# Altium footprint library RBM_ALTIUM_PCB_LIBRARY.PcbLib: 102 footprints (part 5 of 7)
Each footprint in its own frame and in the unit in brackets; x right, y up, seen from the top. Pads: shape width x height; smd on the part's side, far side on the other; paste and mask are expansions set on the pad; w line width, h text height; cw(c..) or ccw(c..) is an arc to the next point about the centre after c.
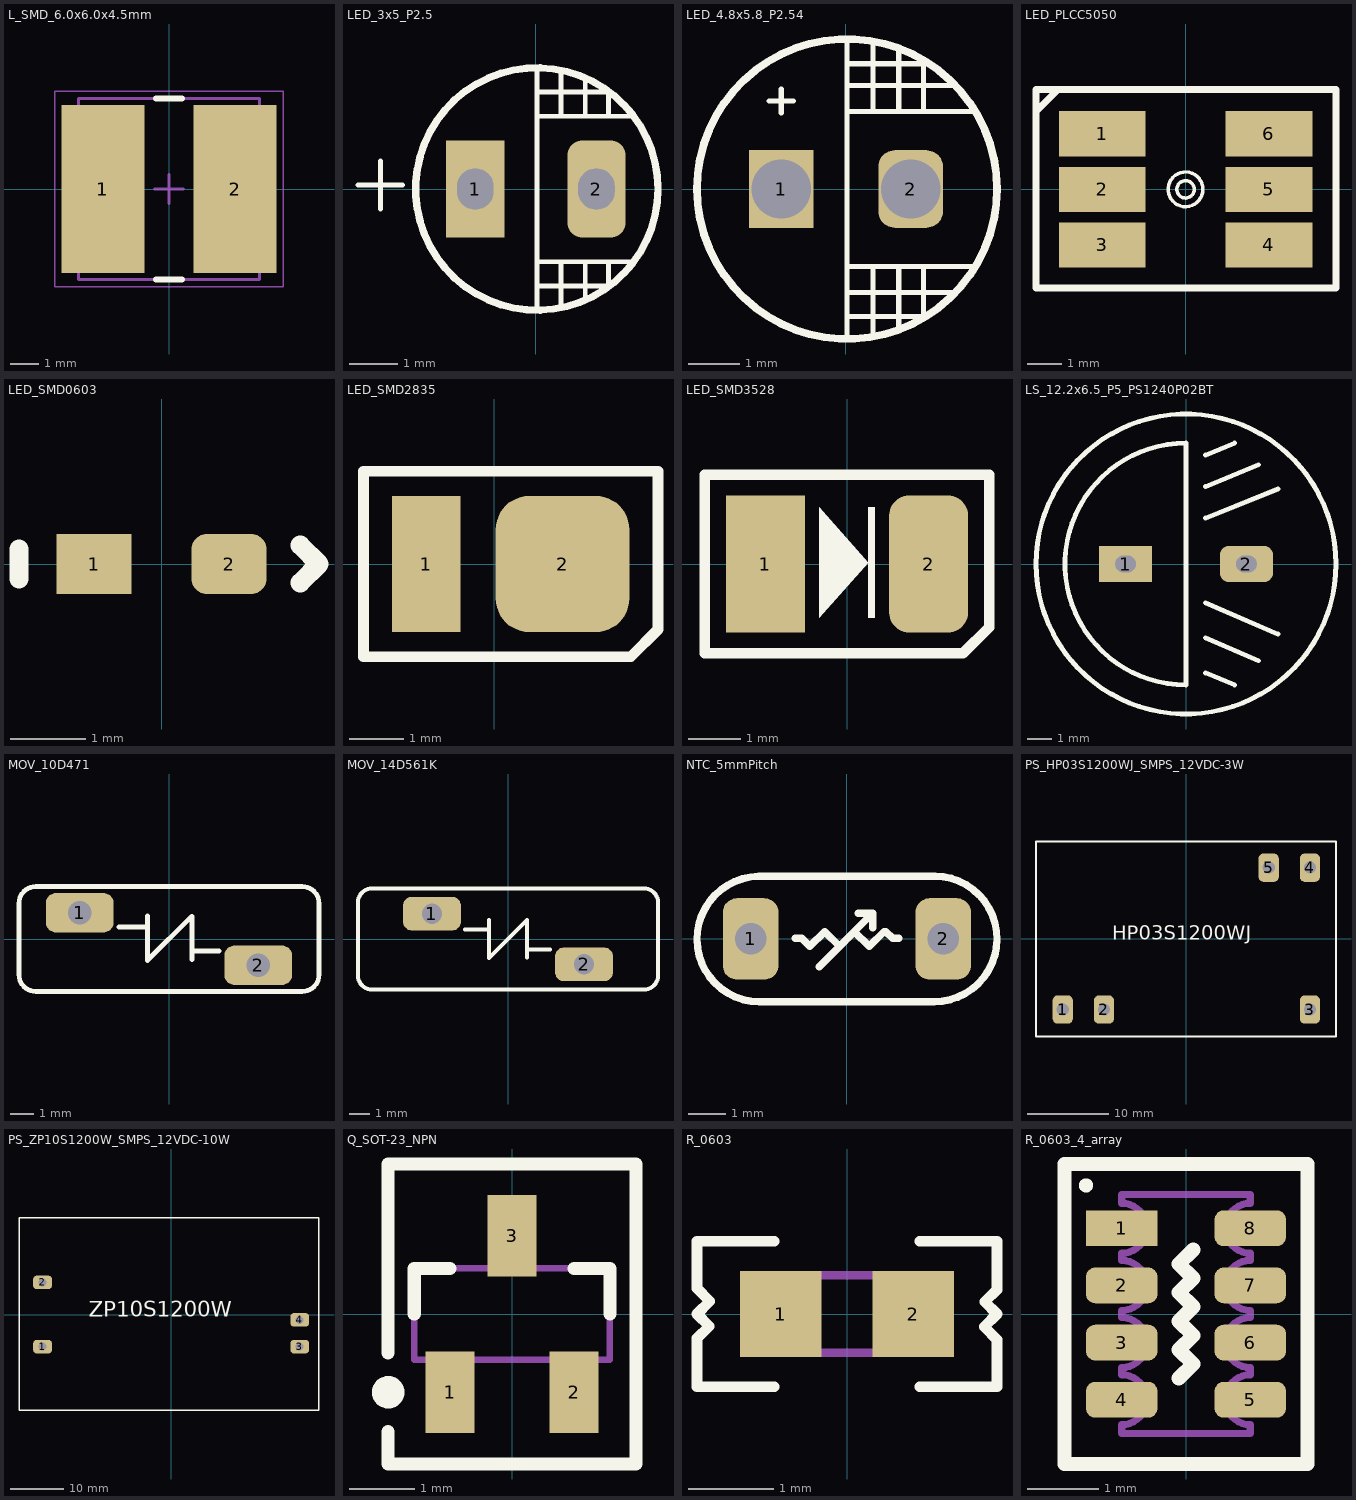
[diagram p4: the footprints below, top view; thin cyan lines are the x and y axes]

## L_SMD_6.0x6.0x4.5mm [mm] "YNR6045-102M;  1mH ±20% 300mA 4.5O SMD,6.0x6.0x4.5mm Power Inductors RoHS"
height 4.5
pads (2):
  rect 2.9x5.85 smd: 1(-2.3,0) 2(2.3,0)
Top Overlay:
  lines w0.2: -0.45,-3.15 0.45,-3.15 ; -0.45,3.15 0.45,3.15
Assembly Top:
  lines w0.1: -3.15,-3.15 -3.15,3.15 3.15,3.15 3.15,-3.15 -3.15,-3.15
Courtyard Top:
  lines w0.05: -3.975,-3.4 -3.975,3.4 3.975,3.4 3.975,-3.4 -3.975,-3.4
  lines w0.1: -0.5,0 0.5,0 ; 0,-0.5 0,0.5
3D body "INDP6060X45N.step": height 4.6, standoff 0, extent -3.1,-3 3.1,3

## LED_3x5_P2.5 [mm]
pads (2):
  rect 1.2x2 hole 0.85 slot 0.75 at 0 deg: 1(-1.25,0)
  rrect50% 1.2x2 hole 0.85 slot 0.75 at 0 deg: 2(1.25,0)
Top Overlay:
  circle w0.15: c0.02,0 r2.5
  lines w0.1: -3.67,0.083 -2.754,0.083 ; -3.203,-0.417 -3.203,0.583 ; 0.02,-2.5 0.02,2.5 ; 0.02,-2 1.5,-2 1.5,-1.5 ; 0.02,-1.5 2.014,-1.5 ; 0.02,1.5 2.014,1.5 ; 0.02,2 1.5,2 1.5,1.5 ; 0.52,-2.4 0.52,-1.5 ; 0.52,1.5 0.52,2.4 ; 1.02,-2.3 1.02,-1.5 ; 1.02,1.5 1.02,2.3
3D body "LED_3x5_P2.5.STEP": height 7.38, standoff -1.17, extent -1.974,-1.498 2.014,1.994

## LED_4.8x5.8_P2.54 [mm] "HL-798H256WC-MD"
pads (2):
  rect 1.25x1.5 / inner rect 1.5x2.2 / far side rect 1.5x2.2 hole 1.15: 1(-1.25,0)
  rrect50% 1.25x1.5 / inner rrect50% 1.5x2.2 / far side rrect50% 1.5x2.2 hole 1.15: 2(1.25,0)
Top Overlay:
  circle w0.15: c0.02,0 r2.9
  lines w0.1: -1.484,1.7 -1.017,1.7 ; -1.25,1.466 -1.25,1.934 ; 0.02,-2.9 0.02,2.9 ; 0.02,-2 2.1,-2 ; 0.02,-1.5 2.503,-1.5 ; 0.02,1.5 2.502,1.5 ; 0.02,2 2.126,2 ; 0.02,2.423 1.5,2.423 ; 0.039,-2.465 1.5,-2.465 ; 0.52,-2.857 0.52,-1.5 ; 0.52,1.5 0.52,2.857 ; 1.02,-2.722 1.02,-1.5 ; 1.02,1.5 1.02,2.722 ; 1.5,-2.494 1.5,-1.5 ; 1.5,1.5 1.5,2.5
3D body: height 4.8, standoff 0, extent -2.38,-2.4 2.42,2.4
3D body: height 1.5, standoff 0, extent -2.88,-2.897 2.92,2.897
3D body: height 2, standoff 1, extent -1.98,-2 2.02,2
3D body: height 1, standoff -1.5, extent -1.746,-0.499 -0.75,0.499
3D body: height 1, standoff -1.5, extent 0.754,-0.499 1.75,0.499

## LED_PLCC5050 [mm] "EDISON RGB .2W"
pads (6):
  rect 2.5x1.3 smd: 1(-2.4,1.6) 2(-2.4,0) 3(-2.4,-1.6) 4(2.4,-1.6) 5(2.4,0) 6(2.4,1.6)
Top Overlay:
  circle w0.1: c0,0 r0.5
  circle w0.1: c0,0 r0.25
  lines w0.2: -4.305,2.235 -3.67,2.87 ; -4.305,-2.845 4.331,-2.845 4.331,2.87 -4.305,2.87 -4.305,-2.845
3D body "User Library-APA102C.step": height 1.51, standoff -0.04, extent -2.75,-2.5 2.75,2.5

## LED_SMD0603 [mm]
pads (2):
  rect 1x0.8 smd: 1(-0.9,0)
  rrect50% 1x0.8 smd: 2(0.9,0)
Top Overlay:
  lines w0.254: -1.9,-0.2 -1.9,0.2 ; 1.85,-0.25 2.1,0 1.85,0.25
3D body "ALSRobot-LED0603(R).step": height 0.6, standoff 0, extent -0.81,-0.4 0.81,0.4

## LED_SMD2835 [mm]
pads (2):
  rect 1.25x2.5 smd: 1(-1.25,0)
  rrect50% 2.45x2.5 smd: 2(1.25,0)
Top Overlay:
  lines w0.2: -2.4,-1.7 2.5,-1.7 3,-1.2 3,1.7 -2.4,1.7 -2.4,-1.7
3D body "LED_SMD-2835.STEP": height 0.7, standoff -0.02, extent -1.547,-1.4 2.017,1.4

## LED_SMD3528 [mm]
pads (2):
  rect 1.5x2.6 smd: 1(-1.55,0)
  rrect50% 1.5x2.6 smd: 2(1.55,0)
Top Overlay:
  region: 0.525,1.075 0.4,1.075 0.4,-1.025 0.525,-1.025
  region: -0.525,-1.025 -0.525,1.075 0.4,0.025
  region: 2.5,1.6
  lines w0.2: -2.7,-1.7 -2.7,1.7 2.7,1.7 2.7,-1.2 2.2,-1.7 -2.7,-1.7
3D body "LED_Osram_Led_PLCC4-2.step": height 1.95, standoff 0, extent -1.8,-1.4 1.7,1.4

## LS_12.2x6.5_P5_PS1240P02BT [mm] "PS1240P02BT, ø12.2x6.5 P5 70dB 4kHz 3~30V"
pads (2):
  rect 2.2x1.5 hole 0.7 slot 0.85 at 0 deg: 1(-2.5,0)
  rrect50% 2.2x1.5 hole 0.7 slot 0.85 at 0 deg: 2(2.5,0)
Top Overlay:
  circle w0.2: c0,0 r6.2
  lines w0.2: 0.8,-4.5 2,-5 ; 0.8,-3.046 3,-4 ; 0.8,-1.6 3.8,-2.9 ; 0.8,1.9 3.8,3.1 ; 0.8,3.2 3,4.1 ; 0.8,4.5 2,5 ; 0,-5 cw(c0,0) 0,5 0,-5
3D body: height 6.8, standoff 0.3, extent -1.494,-1.497 1.494,1.497
3D body: height 1, standoff -1, extent 2.173,-0.329 2.83,0.33
3D body: height 1, standoff -1, extent -2.829,-0.329 -2.171,0.329
3D body: height 6.75, standoff 0.25, extent -6.1,-6.097 6.1,6.097

## MOV_10D471 [mm]
pads (2):
  rrect50% 2.85x1.65 hole 1: 1(-3.75,1.1) 2(3.75,-1.1)
Top Overlay:
  lines w0.1: 0.998,-0.51 1.009,-0.5
  lines w0.2: -5.1,2.2 5.6,2.2 cw(c5.6,1.5) 6.3,1.5 6.3,-1.5 cw(c5.6,-1.5) 5.6,-2.2 -5.6,-2.2 cw(c-5.6,-1.5) -6.3,-1.5 -6.3,1.5 cw(c-5.6,1.5) -5.6,2.2 -4.9,2.2 ; -2.1,0.499 -0.921,0.499 ; -0.908,0.967 -0.908,-0.903 0.954,0.959 ; 0.967,-0.875 0.967,0.959 ; 1.009,-0.5 2.1,-0.5
3D body: height 3, standoff -2, extent 3.343,-1.509 4.16,-0.691
3D body: height 3, standoff -2, extent -4.158,0.691 -3.342,1.509
3D body "User Library-S10K275.STEP": height 13.55, standoff -1.95, extent -6,-1.9 6,1.901

## MOV_14D561K [mm]
pads (2):
  rrect50% 2.85x1.65 hole 1: 1(-3.75,1.25) 2(3.75,-1.25)
Top Overlay:
  lines w0.1: 0.975,-0.539 0.985,-0.528
  lines w0.2: -2.123,0.471 -0.945,0.471 ; -0.931,0.939 -0.931,-0.931 0.931,0.931 ; 0.944,-0.903 0.944,0.931 ; 0.985,-0.528 2.077,-0.528 ; -7.4,-1.8 ccw(c-6.7,-1.8) -6.7,-2.5 6.7,-2.5 ccw(c6.7,-1.8) 7.4,-1.8 7.4,1.8 ccw(c6.7,1.8) 6.7,2.5 -6.7,2.5 ccw(c-6.7,1.8) -7.4,1.8 -7.4,-1.8
3D body "Varistor_14D561K.STEP": height 17.4, standoff -1.5, extent -7.4,-2.175 7.4,2.175

## NTC_5mmPitch [mm]
pads (2):
  rrect50% 1.5x2.2 hole 0.85: 1(-2.6,0) 2(2.6,0)
Top Overlay:
  lines w0.1: -1.229,0.018 -1.218,0.018 ; 1,0.2 1.049,0.2 ; -0.6,0.2 -0.6,0.2 ; 0.6,-0.2 0.6,-0.2
  lines w0.2: -2.384,1.691 ccw(c-2.353,-0.005) -2.371,-1.7 ; -2.384,1.692 2.38,1.692 ; -2.353,-1.694 2.355,-1.694 ; -1.4,0.018 -1.229,0.018 ; -1.218,0.018 -1,-0.2 -0.6,0.2 -0.2,-0.2 0.2,0.2 0.6,-0.2 1,0.2 ; -0.75,-0.75 0.7,0.7 ; 0.3,0.7 0.7,0.7 ; 0.7,0.3 0.7,0.7 ; 1.049,0.2 1.232,0.018 1.4,0.018 ; 2.347,-1.694 ccw(c2.355,0.002) 2.38,1.698
3D body: height 4, standoff 1, extent 2.302,-0.299 2.9,0.3
3D body: height 4, standoff 1, extent -2.9,-0.3 -2.302,0.299
3D body: height 6.75, standoff 1.25, extent -2.752,-1.638 2.748,1.692
3D body: height 2, standoff -1, extent 2.327,-0.274 2.875,0.275
3D body: height 2, standoff -1, extent -2.874,-0.274 -2.326,0.274

## PS_HP03S1200WJ_SMPS_12VDC-3W [mm]
pads (5):
  rrect50% 2.5x3.5 hole 1.5: 1(-15.24,-8.75) 2(-10.16,-8.75) 3(15.24,-8.75) 4(15.24,8.75) 5(10.16,8.75)
Top Overlay:
  lines w0.254: -18.54,-12.05 18.46,-12.05 18.46,11.95 -18.54,11.95 -18.54,-12.05
  text "HP03S1200WJ" at -9.14,-0.75 h3
Bottom Overlay:
  lines w0.254: -18.54,-12.05 18.46,-12.05 18.46,11.95 -18.54,11.95 -18.54,-12.05
  text "L" at -14.24,-6.05 h3
  text "N" at -9.04,-6.05 h3
  text "V" at 11.36,4.15 h3
  text "G" at 16.31,4.1 h3
3D body: height 6, standoff -4, extent -10.656,-9.249 -9.66,-8.251
3D body: height 6, standoff -4, extent -15.736,-9.249 -14.74,-8.251
3D body: height 6, standoff -4, extent 14.744,-9.249 15.74,-8.251
3D body: height 6, standoff -4, extent 14.744,8.251 15.74,9.249
3D body: height 15.5, standoff 0, extent -18.54,-12.05 18.36,11.95
3D body: height 6, standoff -4, extent 9.664,8.251 10.66,9.249

## PS_ZP10S1200W_SMPS_12VDC-10W [mm]
pads (4):
  rrect50% 3.5x2.5 hole 1.5: 1(-24,-6) 2(-24,6) 3(24,-6) 4(24,-1)
Top Overlay:
  lines w0.254: -28.4,-17.9 27.6,-17.9 27.6,18.1 -28.4,18.1 -28.4,-17.9
  text "ZP10S1200W" at -15.4,-1.4 h5
Bottom Overlay:
  lines w0.254: -28.4,-17.9 27.6,-17.9 27.6,18.1 -28.4,18.1 -28.4,-17.9
  text "L" at -17.9,-6.7 h3
  text "N" at -18,5 h3
  text "+Ve" at 20.4,-7 h3
  text "-Ve" at 20.3,-1.7 h3
3D body: height 21, standoff -4, extent -24.496,5.501 -23.5,6.499
3D body: height 21, standoff -4, extent -24.496,-6.499 -23.5,-5.501
3D body: height 21, standoff -4, extent 23.504,-1.499 24.5,-0.501
3D body: height 21, standoff -4, extent 23.504,-6.499 24.5,-5.501
3D body: height 25, standoff 0, extent -28.4,-17.9 27.6,18.1

## Q_SOT-23_NPN [mm] "NPN 200mA 40V 250mW SOT-23(SOT-23-3)"
height 1.15
pads (3):
  rect 0.75x1.25 smd: 1(-0.95,-1.2) 2(0.95,-1.2) 3(0,1.2)
Top Overlay:
  circle w0.25: c-1.9,-1.2 r0.125
  lines w0.2: -1.9,-1.8 -1.9,-2.3 1.9,-2.3 1.9,2.3 -1.9,2.3 -1.9,-0.6 ; -1.5,0 -1.5,0.7 -0.95,0.7 ; 0.95,0.7 1.5,0.7 1.5,0
Mechanical 13:
  lines w0.1: -1.5,-0.7 -1.5,0.7 1.5,0.7 1.5,-0.7 -1.5,-0.7
3D body "SOT95P245X115-3N.step": height 1.15, standoff 0, extent -1.5,-1.3 1.5,1.3

## R_0603 [mm] "RK73G1JTTD1000F; 0603 Chip Resistor - Surface Mount RoHS"
height 0.55
pads (2):
  rect 0.95x1 smd: 1(-0.775,0) 2(0.775,0)
Top Overlay:
  lines w0.125: -1.75,-0.85 -1.75,-0.286 ; -1.75,-0.283 -1.609,-0.141 -1.75,0 -1.6,0.15 -1.75,0.3 -1.75,0.85 -0.85,0.85 ; -1.746,-0.85 -0.85,-0.85 ; 0.85,-0.85 1.75,-0.85 1.75,-0.3 1.6,-0.15 1.75,0 1.609,0.141 1.75,0.283 ; 0.85,0.85 1.746,0.85 ; 1.75,0.286 1.75,0.85
Assembly Top:
  lines w0.1: -0.9,-0.45 0.9,-0.45 0.9,0.45 -0.9,0.45 -0.9,-0.45
3D body "R_0603.step": height 0.55, standoff 0, extent -0.9,-0.45 0.9,0.45

## R_0603_4_array [mm] "Chip Array, Concave, 8-Leads, Pitch 0.80mm,  Body 3.20x1.60mm,  IPC Medium Density"
height 0.7
pads (8):
  rect 1x0.5 smd: 1(-0.9,1.2)
  rrect50% 1x0.5 smd: 2(-0.9,0.4) 3(-0.9,-0.4) 4(-0.9,-1.2) 5(0.9,-1.2) 6(0.9,-0.4) 7(0.9,0.4) 8(0.9,1.2)
Top Overlay:
  circle w0.1: c-1.4,1.8 r0.05
  lines w0.2: -0.1,-0.9 0.1,-0.7 -0.1,-0.5 0.1,-0.3 -0.1,-0.1 0.1,0.1 -0.1,0.3 0.1,0.5 -0.1,0.7 0.1,0.9 ; -1.7,-2.1 -1.7,2.1 1.7,2.1 1.7,-2.1 -1.7,-2.1
Mechanical 13:
  lines w0.1: -0.9,-1.675 -0.9,-1.55 ccw(c-0.9,-1.2) -0.9,-0.85 -0.9,-0.75 ccw(c-0.9,-0.4) -0.9,-0.05 -0.9,0.05 ccw(c-0.9,0.4) -0.9,0.75 -0.9,0.85 ccw(c-0.9,1.2) -0.9,1.55 -0.9,1.675 0.9,1.675 0.9,1.55 ccw(c0.9,1.2) 0.9,0.85 0.9,0.75 ccw(c0.9,0.4) 0.9,0.05 0.9,-0.05 ccw(c0.9,-0.4) 0.9,-0.75 0.9,-0.85 ccw(c0.9,-1.2) 0.9,-1.55 0.9,-1.675 -0.9,-1.675
3D body "R_0603_4_array.step": height 0.7, standoff 0, extent -0.95,-1.675 0.95,1.675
